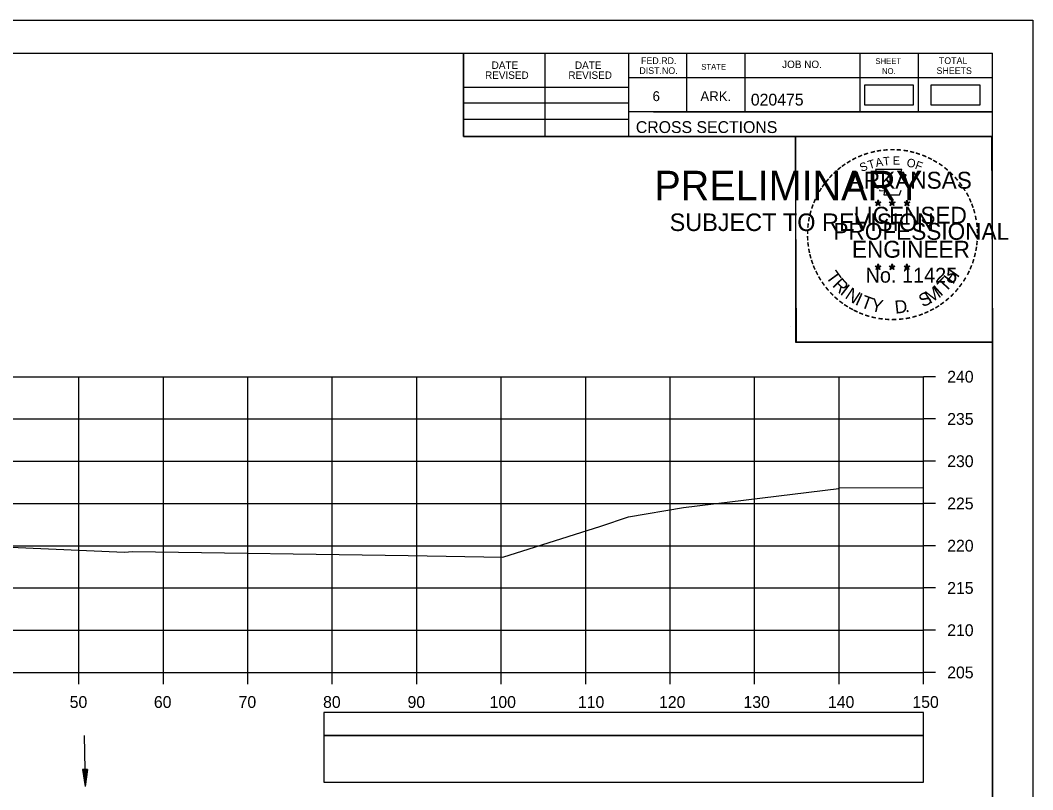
# Model space of a CAD drawing. Extents: x 1386544 to 1388153, y 379785 to 390999.
# Drawn here: x 1387402.7 to 1387522.6, y 387281.1 to 387372.2 of the extents above; entities that cross this region are included whole.
import ezdxf

# ---------------------------------------------------------------- set-up
doc = ezdxf.new("R2010")
doc.units = 0
for name, color, linetype in [('R_Axis', 7, 'Continuous'), ('R_Axis Annot', 7, 'Continuous'), ('R_Border', 7, 'Continuous'), ('R_Border PE', 7, 'Continuous'), ('R_Border Prem', 7, 'Continuous'), ('R_Exist Surface', 7, 'Continuous'), ('R_Grid', 7, 'Continuous'), ('R_No Plot', 7, 'Continuous'), ('R_Water', 7, 'Continuous'), ('S_SHOULDER', 7, 'Continuous')]:
    doc.layers.add(name, color=color, linetype=linetype)

msp = doc.modelspace()

# ---------------------------------------------------------------- linework, layer by layer
at = {"layer": 'R_Axis'}
for p, q in [((1387509.68, 387295.01), (1387509.68, 387330.01)), ((1387511.08, 387330.01), (1387509.68, 387330.01)), ((1387511.08, 387325.01), (1387509.68, 387325.01)), ((1387511.08, 387320.01), (1387509.68, 387320.01)), ((1387511.08, 387315.01), (1387509.68, 387315.01)), ((1387511.08, 387310.01), (1387509.68, 387310.01)), ((1387511.08, 387305.01), (1387509.68, 387305.01)), ((1387511.08, 387300.01), (1387509.68, 387300.01)), ((1387209.68, 387295.01), (1387509.68, 387295.01)), ((1387409.68, 387293.61), (1387409.68, 387295.01)), ((1387419.68, 387293.61), (1387419.68, 387295.01)), ((1387429.68, 387293.61), (1387429.68, 387295.01)), ((1387439.68, 387293.61), (1387439.68, 387295.01)), ((1387449.68, 387293.61), (1387449.68, 387295.01)), ((1387459.68, 387293.61), (1387459.68, 387295.01)), ((1387469.68, 387293.61), (1387469.68, 387295.01)), ((1387479.68, 387293.61), (1387479.68, 387295.01)), ((1387489.68, 387293.61), (1387489.68, 387295.01)), ((1387499.68, 387293.61), (1387499.68, 387295.01)), ((1387509.68, 387293.61), (1387509.68, 387295.01)), ((1387511.08, 387295.01), (1387509.68, 387295.01))]:
    msp.add_line(p, q, dxfattribs=at)
at = {"layer": 'R_Axis Annot'}
for points in [[(1387438.7, 387287.56), (1387509.68, 387287.56), (1387509.68, 387290.27), (1387438.7, 387290.27)], [(1387438.7, 387282.03), (1387509.68, 387282.03), (1387509.68, 387287.56), (1387438.7, 387287.56)]]:
    msp.add_lwpolyline(points, close=True, dxfattribs=at)
at = {"layer": 'R_Border'}
for p, q in [((1387201.68, 387368.3), (1387517.86, 387368.3)), ((1387455.22, 387358.42), (1387455.22, 387368.3)), ((1387464.9, 387358.42), (1387464.9, 387368.3)), ((1387474.76, 387368.3), (1387474.76, 387358.42)), ((1387481.6, 387368.3), (1387481.6, 387361.36)), ((1387488.54, 387368.3), (1387488.54, 387361.36)), ((1387502.12, 387368.3), (1387502.12, 387361.36)), ((1387509.06, 387368.3), (1387509.06, 387361.36)), ((1387517.86, 387162.84), (1387517.86, 387368.3)), ((1387517.86, 387365.36), (1387474.76, 387365.36)), ((1387517.86, 387365.38), (1387517.86, 387365.38)), ((1387455.22, 387364.28), (1387474.76, 387364.28)), ((1387455.22, 387362.42), (1387474.76, 387362.42)), ((1387517.86, 387361.36), (1387474.76, 387361.36)), ((1387477.72, 387361.36), (1387517.86, 387361.36)), ((1387455.22, 387360.48), (1387474.76, 387360.48)), ((1387517.86, 387358.42), (1387455.22, 387358.42))]:
    msp.add_line(p, q, dxfattribs=at)
at = {"layer": 'R_Border PE'}
for p, q in [((1387503.94, 387350.67), (1387504.29, 387350.56)), ((1387503.94, 387350.67), (1387504.19, 387350.63)), ((1387503.94, 387350.67), (1387504.18, 387350.55)), ((1387504.07, 387350.27), (1387504.29, 387350.56)), ((1387504.07, 387350.27), (1387504.2, 387350.51)), ((1387504.07, 387350.27), (1387504.29, 387350.48)), ((1387504.29, 387350.93), (1387504.25, 387350.68)), ((1387504.29, 387350.56), (1387504.29, 387350.93)), ((1387504.29, 387350.93), (1387504.34, 387350.68)), ((1387504.64, 387350.67), (1387504.29, 387350.56)), ((1387504.5, 387350.27), (1387504.29, 387350.56)), ((1387504.5, 387350.27), (1387504.29, 387350.48)), ((1387504.64, 387350.67), (1387504.35, 387350.63)), ((1387504.5, 387350.27), (1387504.37, 387350.56)), ((1387504.64, 387350.67), (1387504.43, 387350.57)), ((1387505.61, 387350.67), (1387505.96, 387350.56)), ((1387505.61, 387350.67), (1387505.86, 387350.63)), ((1387505.61, 387350.67), (1387505.85, 387350.55)), ((1387505.74, 387350.27), (1387505.96, 387350.56)), ((1387505.74, 387350.27), (1387505.87, 387350.51)), ((1387505.74, 387350.27), (1387505.96, 387350.48)), ((1387505.96, 387350.93), (1387505.92, 387350.68)), ((1387505.96, 387350.56), (1387505.96, 387350.93)), ((1387505.96, 387350.93), (1387506.01, 387350.68)), ((1387506.31, 387350.67), (1387505.96, 387350.56)), ((1387506.17, 387350.27), (1387505.96, 387350.56)), ((1387506.17, 387350.27), (1387505.96, 387350.48)), ((1387506.31, 387350.67), (1387506.02, 387350.63)), ((1387506.17, 387350.27), (1387506.04, 387350.56)), ((1387506.31, 387350.67), (1387506.1, 387350.57)), ((1387507.38, 387350.66), (1387507.72, 387350.55)), ((1387507.38, 387350.66), (1387507.63, 387350.62)), ((1387507.38, 387350.66), (1387507.61, 387350.54)), ((1387507.51, 387350.25), (1387507.72, 387350.55)), ((1387507.51, 387350.25), (1387507.63, 387350.5)), ((1387507.51, 387350.25), (1387507.72, 387350.47)), ((1387507.72, 387350.92), (1387507.68, 387350.66)), ((1387507.72, 387350.55), (1387507.72, 387350.92)), ((1387507.72, 387350.92), (1387507.77, 387350.67)), ((1387508.07, 387350.66), (1387507.72, 387350.55)), ((1387507.94, 387350.25), (1387507.72, 387350.55)), ((1387507.94, 387350.25), (1387507.72, 387350.47)), ((1387508.07, 387350.66), (1387507.79, 387350.61)), ((1387507.94, 387350.25), (1387507.8, 387350.55)), ((1387508.07, 387350.66), (1387507.87, 387350.56)), ((1387503.94, 387343.1), (1387504.29, 387342.99)), ((1387503.94, 387343.1), (1387504.19, 387343.06)), ((1387503.94, 387343.1), (1387504.17, 387342.98)), ((1387504.07, 387342.69), (1387504.29, 387342.99)), ((1387504.29, 387343.36), (1387504.25, 387343.1)), ((1387504.29, 387342.99), (1387504.29, 387343.36)), ((1387504.29, 387343.36), (1387504.34, 387343.11)), ((1387504.63, 387343.1), (1387504.29, 387342.99)), ((1387504.5, 387342.69), (1387504.29, 387342.99)), ((1387504.63, 387343.1), (1387504.35, 387343.05)), ((1387504.5, 387342.69), (1387504.36, 387342.98)), ((1387504.63, 387343.1), (1387504.43, 387343)), ((1387505.61, 387343.1), (1387505.96, 387342.99)), ((1387505.61, 387343.1), (1387505.86, 387343.06)), ((1387505.61, 387343.1), (1387505.84, 387342.98)), ((1387505.74, 387342.69), (1387505.96, 387342.99)), ((1387505.96, 387343.36), (1387505.91, 387343.1)), ((1387505.96, 387342.99), (1387505.96, 387343.36)), ((1387505.96, 387343.36), (1387506, 387343.11)), ((1387506.3, 387343.1), (1387505.96, 387342.99)), ((1387506.17, 387342.69), (1387505.96, 387342.99)), ((1387506.3, 387343.1), (1387506.02, 387343.05)), ((1387506.17, 387342.69), (1387506.03, 387342.98)), ((1387506.3, 387343.1), (1387506.1, 387343)), ((1387507.37, 387343.09), (1387507.72, 387342.98)), ((1387507.37, 387343.09), (1387507.63, 387343.05)), ((1387507.37, 387343.09), (1387507.61, 387342.97)), ((1387507.51, 387342.68), (1387507.72, 387342.98)), ((1387507.72, 387343.35), (1387507.68, 387343.09)), ((1387507.72, 387342.98), (1387507.72, 387343.35)), ((1387507.72, 387343.35), (1387507.77, 387343.1)), ((1387508.07, 387343.09), (1387507.72, 387342.98)), ((1387507.94, 387342.68), (1387507.72, 387342.98)), ((1387508.07, 387343.09), (1387507.78, 387343.04)), ((1387508.07, 387343.09), (1387507.87, 387342.99)), ((1387504.07, 387342.69), (1387504.2, 387342.94)), ((1387504.07, 387342.69), (1387504.28, 387342.91)), ((1387504.5, 387342.69), (1387504.28, 387342.91)), ((1387505.74, 387342.69), (1387505.87, 387342.94)), ((1387505.74, 387342.69), (1387505.95, 387342.91)), ((1387506.17, 387342.69), (1387505.95, 387342.91)), ((1387507.51, 387342.68), (1387507.63, 387342.93)), ((1387507.51, 387342.68), (1387507.72, 387342.9)), ((1387507.94, 387342.68), (1387507.72, 387342.9)), ((1387507.94, 387342.68), (1387507.8, 387342.97))]:
    msp.add_line(p, q, dxfattribs=at)
for points in [[(1387503.98, 387354.55), (1387504.25, 387353.73)], [(1387507.49, 387353.63), (1387507.64, 387353.91), (1387506.95, 387353.89), (1387507.1, 387354.55), (1387503.98, 387354.55)], [(1387504.47, 387352.13), (1387504.47, 387352.04), (1387505.04, 387352.02), (1387504.98, 387351.55), (1387506.85, 387351.55), (1387507.05, 387352.09)], [(1387504.29, 387350.93), (1387504.5, 387350.27), (1387503.94, 387350.67), (1387504.64, 387350.67), (1387504.07, 387350.27), (1387504.29, 387350.93)], [(1387505.96, 387350.93), (1387506.17, 387350.27), (1387505.61, 387350.67), (1387506.31, 387350.67), (1387505.74, 387350.27), (1387505.96, 387350.93)], [(1387507.72, 387350.92), (1387507.94, 387350.25), (1387507.38, 387350.66), (1387508.07, 387350.66), (1387507.51, 387350.25), (1387507.72, 387350.92)], [(1387504.29, 387343.36), (1387504.5, 387342.69), (1387503.94, 387343.1), (1387504.63, 387343.1), (1387504.07, 387342.69), (1387504.29, 387343.36)], [(1387505.96, 387343.36), (1387506.17, 387342.69), (1387505.61, 387343.1), (1387506.3, 387343.1), (1387505.74, 387342.69), (1387505.96, 387343.36)], [(1387507.72, 387343.35), (1387507.94, 387342.68), (1387507.37, 387343.09), (1387508.07, 387343.09), (1387507.51, 387342.68), (1387507.72, 387343.35)]]:
    msp.add_lwpolyline(points, dxfattribs=at)
for centre, radius in [((1387504.29, 387350.56), 0.172), ((1387504.29, 387350.56), 0.145), ((1387504.29, 387350.56), 0.116), ((1387504.29, 387350.56), 0.0991), ((1387504.29, 387350.56), 0.0747), ((1387504.29, 387350.56), 0.0495), ((1387504.29, 387350.56), 0.0296), ((1387505.96, 387350.56), 0.172), ((1387505.96, 387350.56), 0.145), ((1387505.96, 387350.56), 0.116), ((1387505.96, 387350.56), 0.0991), ((1387505.96, 387350.56), 0.0747), ((1387505.96, 387350.56), 0.0495), ((1387505.96, 387350.56), 0.0296), ((1387507.72, 387350.55), 0.172), ((1387507.72, 387350.55), 0.145), ((1387507.72, 387350.55), 0.116), ((1387507.72, 387350.55), 0.0991), ((1387507.72, 387350.55), 0.0747), ((1387507.72, 387350.55), 0.0495), ((1387507.72, 387350.55), 0.0296), ((1387504.29, 387342.99), 0.172), ((1387504.29, 387342.99), 0.145), ((1387504.29, 387342.99), 0.116), ((1387504.29, 387342.99), 0.0991), ((1387504.29, 387342.99), 0.0747), ((1387504.29, 387342.99), 0.0495), ((1387504.29, 387342.99), 0.0296), ((1387505.95, 387342.99), 0.172), ((1387505.95, 387342.99), 0.145), ((1387505.95, 387342.99), 0.116), ((1387505.95, 387342.99), 0.0991), ((1387505.95, 387342.99), 0.0747), ((1387505.95, 387342.99), 0.0495), ((1387505.95, 387342.99), 0.0296), ((1387507.72, 387342.98), 0.172), ((1387507.72, 387342.98), 0.145), ((1387507.72, 387342.98), 0.116), ((1387507.72, 387342.98), 0.0991), ((1387507.72, 387342.98), 0.0747), ((1387507.72, 387342.98), 0.0495), ((1387507.72, 387342.98), 0.0296)]:
    msp.add_circle(centre, radius, dxfattribs=at)
at = {"layer": 'R_Exist Surface'}
msp.add_lwpolyline([(1387401.59, 387309.83), (1387415.1, 387309.25), (1387416.01, 387309.31), (1387448.67, 387308.86), (1387459.88, 387308.66), (1387471.49, 387312.34), (1387474.74, 387313.41), (1387481.25, 387314.54), (1387499.65, 387316.76), (1387499.71, 387316.88), (1387509.68, 387316.85)], dxfattribs=at)
at = {"layer": 'R_Grid'}
for p, q in [((1387209.68, 387330.01), (1387509.68, 387330.01)), ((1387409.68, 387295.01), (1387409.68, 387330.01)), ((1387419.68, 387295.01), (1387419.68, 387330.01)), ((1387429.68, 387295.01), (1387429.68, 387330.01)), ((1387439.68, 387295.01), (1387439.68, 387330.01)), ((1387449.68, 387295.01), (1387449.68, 387330.01)), ((1387459.68, 387295.01), (1387459.68, 387330.01)), ((1387469.68, 387295.01), (1387469.68, 387330.01)), ((1387479.68, 387295.01), (1387479.68, 387330.01)), ((1387489.68, 387295.01), (1387489.68, 387330.01)), ((1387499.68, 387295.01), (1387499.68, 387330.01)), ((1387509.68, 387295.01), (1387509.68, 387330.01)), ((1387209.68, 387325.01), (1387509.68, 387325.01)), ((1387209.68, 387320.01), (1387509.68, 387320.01)), ((1387209.68, 387315.01), (1387509.68, 387315.01)), ((1387209.68, 387310.01), (1387509.68, 387310.01)), ((1387209.68, 387305.01), (1387509.68, 387305.01)), ((1387209.68, 387300.01), (1387509.68, 387300.01)), ((1387209.68, 387295.01), (1387509.68, 387295.01))]:
    msp.add_line(p, q, dxfattribs=at)
at = {"layer": 'R_No Plot'}
for p, q in [((1387189.28, 387372.19), (1387522.61, 387372.19)), ((1387493.89, 387335.96), (1387493.89, 387335.96))]:
    msp.add_line(p, q, dxfattribs=at)
for points in [[(1387189.27, 387372.19), (1387522.61, 387372.19), (1387522.61, 387158.86), (1387189.27, 387158.86)], [(1387435.6, 387368.3), (1387455.22, 387368.3), (1387455.22, 387358.42), (1387471.33, 387358.42), (1387494.53, 387358.42), (1387494.53, 387334.09), (1387517.86, 387334.09), (1387517.86, 387162.84), (1387201.68, 387162.84), (1387201.68, 387368.3)], [(1387494.53, 387358.42), (1387517.74, 387358.42), (1387517.86, 387334.09), (1387494.65, 387334.09)]]:
    msp.add_lwpolyline(points, close=True, dxfattribs=at)
at = {"layer": 'R_Water'}
for p, q in [((1387410.32, 387287.53), (1387410.43, 387281.53)), ((1387410.7, 387283.53), (1387410.1, 387283.52)), ((1387410.7, 387283.53), (1387410.1, 387283.52)), ((1387410.1, 387283.52), (1387410.43, 387281.53)), ((1387410.1, 387283.52), (1387410.43, 387281.53)), ((1387410.15, 387283.52), (1387410.43, 387281.86)), ((1387410.15, 387283.52), (1387410.43, 387281.86)), ((1387410.2, 387283.53), (1387410.42, 387282.21)), ((1387410.2, 387283.53), (1387410.42, 387282.21)), ((1387410.25, 387283.53), (1387410.41, 387282.54)), ((1387410.25, 387283.53), (1387410.41, 387282.54)), ((1387410.3, 387283.53), (1387410.41, 387282.88)), ((1387410.3, 387283.53), (1387410.41, 387282.88)), ((1387410.35, 387283.53), (1387410.4, 387283.21)), ((1387410.35, 387283.53), (1387410.4, 387283.21)), ((1387410.44, 387283.53), (1387410.4, 387283.21)), ((1387410.44, 387283.53), (1387410.4, 387283.21)), ((1387410.49, 387283.53), (1387410.41, 387282.88)), ((1387410.54, 387283.53), (1387410.41, 387282.54)), ((1387410.49, 387283.53), (1387410.41, 387282.88)), ((1387410.54, 387283.53), (1387410.41, 387282.54)), ((1387410.59, 387283.53), (1387410.42, 387282.21)), ((1387410.59, 387283.53), (1387410.42, 387282.21)), ((1387410.7, 387283.53), (1387410.43, 387281.53)), ((1387410.65, 387283.53), (1387410.43, 387281.86)), ((1387410.7, 387283.53), (1387410.43, 387281.53)), ((1387410.65, 387283.53), (1387410.43, 387281.86))]:
    msp.add_line(p, q, dxfattribs=at)
at = {"layer": 'S_SHOULDER'}
for points in [[(1387502.67, 387362.2), (1387508.5, 387362.2), (1387508.5, 387364.51), (1387502.67, 387364.51)], [(1387510.54, 387362.2), (1387516.37, 387362.2), (1387516.37, 387364.51), (1387510.54, 387364.51)]]:
    msp.add_lwpolyline(points, close=True, dxfattribs=at)

# ---------------------------------------------------------------- texts
at = {"layer": 'R_Axis Annot'}
for s, p in [('240', (1387512.48, 387329.31)), ('235', (1387512.48, 387324.31)), ('230', (1387512.48, 387319.31)), ('225', (1387512.48, 387314.31)), ('220', (1387512.48, 387309.31)), ('215', (1387512.48, 387304.31)), ('210', (1387512.48, 387299.31)), ('205', (1387512.48, 387294.31)), ('50', (1387408.59, 387290.81)), ('60', (1387418.56, 387290.81)), ('70', (1387428.59, 387290.81)), ('80', (1387438.59, 387290.81)), ('90', (1387448.59, 387290.81)), ('100', (1387458.3, 387290.81)), ('110', (1387468.76, 387290.81)), ('120', (1387478.36, 387290.81)), ('130', (1387488.36, 387290.81)), ('140', (1387498.36, 387290.81)), ('150', (1387508.36, 387290.81))]:
    msp.add_text(s, height=1.4, dxfattribs=at).set_placement(p)
at = {"layer": 'R_Border'}
for s, height, p in [('DATE', 0.879, (1387458.55, 387366.44)), ('DATE', 0.879, (1387468.41, 387366.44)), ('FED.RD.', 0.782, (1387476.24, 387367.02)), ('STATE', 0.684, (1387483.36, 387366.34)), ('JOB NO.', 0.879, (1387492.94, 387366.54)), ('SHEET', 0.684, (1387503.98, 387367.02)), ('TOTAL', 0.782, (1387511.5, 387367.02)), ('REVISED', 0.879, (1387457.77, 387365.26)), ('REVISED', 0.879, (1387467.63, 387365.26)), ('DIST.NO.', 0.782, (1387476.04, 387365.84)), ('NO.', 0.684, (1387504.76, 387365.84)), ('SHEETS', 0.782, (1387511.22, 387365.84)), ('6', 1.17, (1387477.6, 387362.62)), ('ARK.', 1.172, (1387483.26, 387362.62)), ('020475', 1.4, (1387489.23, 387362.1)), ('CROSS SECTIONS', 1.4, (1387475.62, 387358.85))]:
    msp.add_text(s, height=height, rotation=360, dxfattribs=at).set_placement(p)
at = {"layer": 'R_Border PE'}
for s, height, rotation, p in [('-', 1.6, 24.3072, (1387502.1, 387355.41)), ('-', 1.6, 19.1761, (1387502.73, 387355.68)), ('-', 1.6, 13.6301, (1387503.48, 387355.92)), ('-', 1.6, 10.2193, (1387504.16, 387356.08)), ('-', 1.6, 5.8968, (1387504.89, 387356.19)), ('-', 1.6, 0.1862, (1387505.66, 387356.26)), ('-', 1.6, 357.743, (1387506.38, 387356.25)), ('-', 1.6, 352.1617, (1387507.13, 387356.2)), ('-', 1.6, 347.2049, (1387507.84, 387356.08)), ('-', 1.6, 342.3362, (1387508.48, 387355.93)), ('-', 1.6, 337.8551, (1387509.21, 387355.7)), ('-', 1.6, 36.2317, (1387500.29, 387354.33)), ('-', 1.6, 34.0636, (1387500.87, 387354.72)), ('-', 1.6, 28.7918, (1387501.46, 387355.09)), ('S', 1, 21.594, (1387502.34, 387354.23)), ('T', 1, 16.4036, (1387503.25, 387354.56)), ('A', 1, 11.2132, (1387504.08, 387354.81)), ('T', 1, 6.0228, (1387504.93, 387354.98)), ('E', 1, 0.8323, (1387506.03, 387355.09)), ('O', 1, 350.4515, (1387507.63, 387354.88)), ('F', 1, 340.0707, (1387508.59, 387354.65)), ('-', 1.6, 334.1211, (1387509.85, 387355.43)), ('-', 1.6, 329.6409, (1387510.42, 387355.15)), ('-', 1.6, 325.8627, (1387511.07, 387354.79)), ('-', 1.6, 48.423, (1387498.93, 387353.06)), ('-', 1.6, 42.9622, (1387499.38, 387353.53)), ('-', 1.6, 38.9507, (1387499.81, 387353.95)), ('ARKANSAS', 2, 360, (1387500.83, 387352.26)), ('-', 1.6, 320.5297, (1387511.68, 387354.36)), ('-', 1.6, 315.5786, (1387512.28, 387353.87)), ('-', 1.6, 54.2325, (1387498.11, 387352)), ('-', 1.6, 50.6142, (1387498.53, 387352.57)), ('-', 1.6, 309.8797, (1387512.85, 387353.32)), ('-', 1.6, 306.6522, (1387513.37, 387352.72)), ('-', 1.6, 62.8713, (1387497.48, 387350.86)), ('-', 1.6, 58.0706, (1387497.79, 387351.48)), ('-', 1.4, 303.6753, (1387513.86, 387352.15)), ('-', 1.6, 299.6684, (1387514.18, 387351.55)), ('-', 1.6, 72.3945, (1387497, 387349.62)), ('-', 1.6, 67.7743, (1387497.22, 387350.25)), ('DWB', 0.01, 360, (1387504.28, 387350.56)), ('DWB', 0.01, 360, (1387505.95, 387350.56)), ('DWB', 0.01, 360, (1387507.71, 387350.55)), ('-', 1.6, 294.6628, (1387514.5, 387350.94)), ('-', 1.6, 290.5728, (1387514.76, 387350.36)), ('-', 1.6, 75.461, (1387496.8, 387348.91)), ('LICENSED', 2, 360, (1387501.43, 387348.12)), ('-', 1.6, 285.1233, (1387514.99, 387349.78)), ('-', 1.6, 280.5493, (1387515.19, 387349.04)), ('-', 1.6, 85.1863, (1387496.59, 387347.5)), ('-', 1.6, 81.2013, (1387496.67, 387348.19)), ('PROFESSIONAL', 2, 360, (1387499.01, 387346.21)), ('-', 1.6, 276.5962, (1387515.35, 387348.27)), ('-', 1.6, 94.1959, (1387496.6, 387346.08)), ('-', 1.6, 89.0622, (1387496.57, 387346.8)), ('-', 1.6, 274.3301, (1387515.41, 387347.55)), ('-', 1.6, 269.9407, (1387515.45, 387346.91)), ('-', 1.6, 98.9479, (1387496.68, 387345.41)), ('ENGINEER', 2, 360, (1387501.2, 387344.09)), ('-', 1.6, 260.9953, (1387515.36, 387345.59)), ('-', 1.6, 263.5172, (1387515.43, 387346.25)), ('-', 1.6, 101.7149, (1387496.81, 387344.68)), ('-', 1.6, 105.4578, (1387496.97, 387344.08)), ('-', 1.6, 255.7626, (1387515.25, 387344.92)), ('-', 1.6, 109.0874, (1387497.19, 387343.45)), ('-', 1.6, 114.0643, (1387497.44, 387342.85)), ('DWB', 0.01, 360, (1387504.27, 387342.98)), ('DWB', 0.01, 360, (1387505.94, 387342.99)), ('DWB', 0.01, 360, (1387507.71, 387342.98)), ('-', 1.6, 247.8887, (1387514.84, 387343.52)), ('-', 1.6, 252.8681, (1387515.07, 387344.2)), ('-', 1.6, 115.7289, (1387497.75, 387342.24)), ('-', 1.6, 120.4471, (1387498.1, 387341.65)), ('T', 1.54, 306.0406, (1387498.05, 387341.83)), ('No. 11425', 1.757, 360, (1387502.82, 387341.14)), ('T', 1.54, 46.6444, (1387512.28, 387339.92)), ('H', 1.54, 54.6088, (1387513.17, 387340.86)), ('-', 1.6, 239.0712, (1387514.19, 387342.14)), ('-', 1.6, 244.6197, (1387514.58, 387342.89)), ('-', 1.6, 125.8934, (1387498.51, 387341.09)), ('-', 1.6, 130.7181, (1387498.97, 387340.54)), ('R', 1.54, 314.005, (1387498.81, 387340.78)), ('I', 1.54, 321.9694, (1387499.71, 387339.85)), ('M', 1.54, 32.6563, (1387510.43, 387338.6)), ('I', 1.54, 42.1136, (1387511.71, 387339.44)), ('-', 1.6, 233.8452, (1387513.78, 387341.49)), ('-', 1.6, 134.2238, (1387499.49, 387339.99)), ('-', 1.6, 138.9338, (1387500.01, 387339.53)), ('N', 1.54, 326.5002, (1387500.28, 387339.38)), ('I', 1.54, 335.3603, (1387501.48, 387338.59)), ('T', 1.54, 339.8912, (1387502.14, 387338.26)), ('S', 1.54, 26.9312, (1387509.59, 387338.19)), ('-', 1.6, 221.0851, (1387512.35, 387339.85)), ('-', 1.6, 225.7653, (1387512.88, 387340.36)), ('-', 1.6, 231.2538, (1387513.35, 387340.92)), ('-', 1.6, 144.6463, (1387500.57, 387339.12)), ('-', 1.6, 148.0898, (1387501.13, 387338.75)), ('-', 1.6, 151.5704, (1387501.71, 387338.43)), ('Y', 1.54, 347.8556, (1387503.36, 387337.82)), ('D', 1.54, 6.3969, (1387506.35, 387337.46)), ('-', 1.6, 212.2491, (1387511.27, 387338.99)), ('-', 1.6, 215.7363, (1387511.8, 387339.38)), ('-', 1.6, 154.6002, (1387502.23, 387338.18)), ('-', 1.6, 158.5612, (1387502.85, 387337.93)), ('-', 1.6, 162.7983, (1387503.54, 387337.71)), ('-', 1.6, 167.5555, (1387504.25, 387337.55)), ('-', 1.6, 173.1155, (1387505.03, 387337.44)), ('-', 1.6, 191.2858, (1387508.06, 387337.61)), ('.', 1.54, 13.7642, (1387507.54, 387337.59)), ('-', 1.6, 195.4743, (1387508.79, 387337.81)), ('-', 1.6, 200.7184, (1387509.47, 387338.05)), ('-', 1.6, 204.2516, (1387510.09, 387338.33)), ('-', 1.6, 207.3568, (1387510.71, 387338.65)), ('-', 1.6, 176.5183, (1387505.77, 387337.39)), ('-', 1.6, 181.5918, (1387506.52, 387337.4)), ('-', 1.6, 185.8167, (1387507.33, 387337.48))]:
    msp.add_text(s, height=height, rotation=rotation, dxfattribs=at).set_placement(p)
at = {"layer": 'R_Border Prem'}
for s, height, p in [('PRELIMINARY', 3.5, (1387477.81, 387350.88)), ('DWB', 0.01, (1387478.55, 387352.73)), ('SUBJECT TO REVISION', 2.0751, (1387479.62, 387347.25))]:
    msp.add_text(s, height=height, rotation=360, dxfattribs=at).set_placement(p)

doc.saveas('drawing.dxf')
